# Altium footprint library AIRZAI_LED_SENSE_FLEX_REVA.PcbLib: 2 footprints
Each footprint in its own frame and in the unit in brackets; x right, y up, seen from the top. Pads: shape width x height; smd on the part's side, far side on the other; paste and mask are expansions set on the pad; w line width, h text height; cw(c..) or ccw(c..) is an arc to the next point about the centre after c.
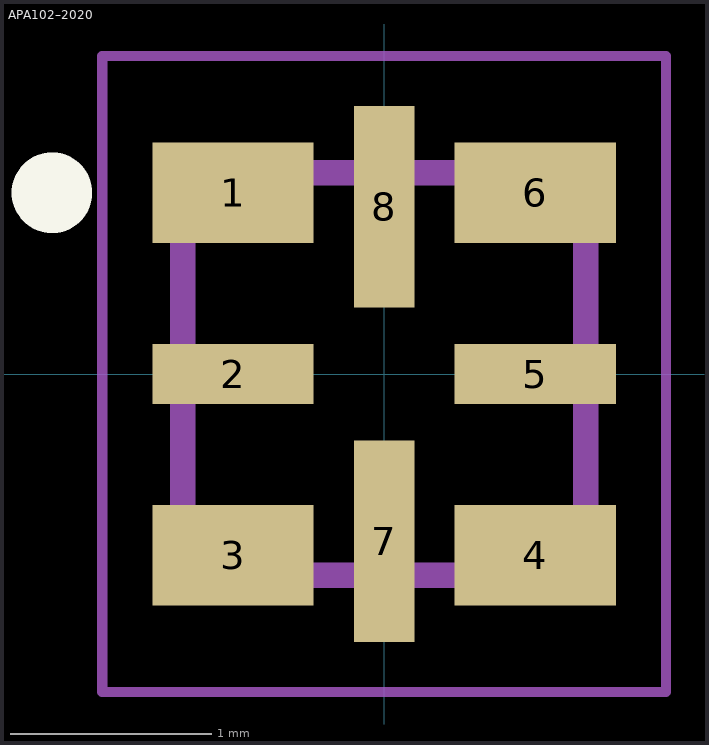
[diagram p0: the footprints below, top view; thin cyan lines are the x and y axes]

## APA102–2020 [mm]
pads (8):
  rect 0.8x0.5 smd: 1(-0.75,0.9) 3(-0.75,-0.9) 4(0.75,-0.9) 6(0.75,0.9)
  rect 0.8x0.3 smd: 2(-0.75,0) 5(0.75,0)
  rect 0.3x1 smd: 7(0,-0.83) 8(0,0.83)
Top Overlay:
  circle w0.3: c-1.65,0.9 r0.05
  circle w0.3: c-1.65,0.9 r0.05
Mechanical 13 (Mech13):
  lines w0.127: -1,-1 1,-1 1,1 -1,1 -1,-1
Mechanical 16:
  lines w0.05: -1.4,-1.58 1.4,-1.58 1.4,1.58 -1.4,1.58 -1.4,-1.58
3D body: height 0.94, standoff 0, extent 0.318,-0.762 0.699,-0.254
3D body: height 0.94, standoff 0, extent -0.19,-0.762 0.191,-0.254
3D body: height 0.94, standoff 0, extent -0.698,-0.762 -0.317,-0.254
3D body: height 0.91, standoff 0, extent -1,-1 1,1

## PCBComponent_1 [mm]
